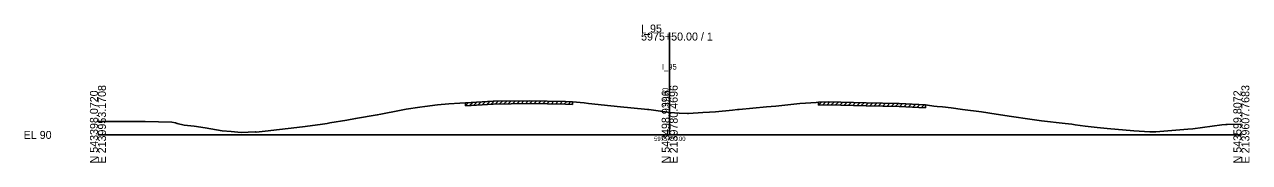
# Model space of a CAD drawing. Extents: x -12534 to 3403, y -1332 to 21983.
# Drawn here: x -25.7 to 402.8, y 10490.3 to 10538.7 of the extents above; entities that cross this region are included whole.
import ezdxf

# ---------------------------------------------------------------- set-up
doc = ezdxf.new("R2010")
doc.units = 0
for name, color, linetype in [('RD_GPK_XS_Cell', 7, 'Continuous'), ('RD_XS_ExGround', 7, 'Continuous'), ('RD_XS_ExPaveRet', 7, 'Continuous'), ('RD_XS_TX_Baseline', 7, 'Continuous'), ('RD_XS_TX_Elev_EX', 7, 'Continuous'), ('RD_XS_TX_Station', 7, 'Continuous')]:
    doc.layers.add(name, color=color, linetype=linetype)

msp = doc.modelspace()

# ---------------------------------------------------------------- linework, layer by layer
at = {"layer": 'RD_GPK_XS_Cell'}
for p, q in [((200, 10500), (200, 10535.9)), ((0, 10500), (200, 10500)), ((200, 10500), (400, 10500))]:
    msp.add_line(p, q, dxfattribs=at)
at = {"layer": 'RD_XS_ExGround'}
msp.add_lwpolyline([(0, 10504.65), (3.21, 10504.72), (6.72, 10504.76), (11.37, 10504.66), (16.54, 10504.66), (25.79, 10504.46), (27.18, 10504.26), (27.72, 10504), (30.17, 10503.47), (33.67, 10503.11), (37.47, 10502.48), (43.49, 10501.41), (46.58, 10501.24), (50.15, 10500.83), (54.96, 10501.08), (55.33, 10500.98), (58.45, 10501.27), (71.58, 10502.87), (77.73, 10503.71), (80.16, 10504.06), (81.1, 10504.23), (87.05, 10505.2), (90.13, 10505.7), (97.69, 10507.02), (98.97, 10507.28), (105.51, 10508.6), (107.79, 10508.99), (112.61, 10509.75), (114.37, 10510.02), (118.81, 10510.58), (122.7, 10510.92), (126.56, 10511.15), (128.53, 10511.25), (138.29, 10511.84), (150.82, 10511.97), (163.61, 10511.76), (165.97, 10511.66), (170.05, 10511.26), (171.63, 10511.01), (179.42, 10510.24), (182.76, 10509.87), (191.22, 10509.03), (192.3, 10508.92), (192.67, 10508.88), (200.1, 10507.89), (203.27, 10507.59), (206.19, 10507.54), (206.64, 10507.54), (211.57, 10507.84), (213.96, 10507.93), (216.02, 10508.13), (221.97, 10508.72), (223.72, 10508.89), (224.3, 10508.94), (233.87, 10509.81), (237.18, 10510.12), (245.53, 10510.96), (247.5, 10511.14), (251.27, 10511.37), (252.05, 10511.45), (255.46, 10511.59), (268.7, 10511.25), (280.29, 10511.02), (289.48, 10510.53), (290.21, 10510.4), (292.42, 10510.11), (293.53, 10510), (295.49, 10509.82), (298.43, 10509.45), (302.48, 10508.89), (309.09, 10508.06), (314.22, 10507.28), (319.58, 10506.44), (326, 10505.54), (330.09, 10504.99), (338.4, 10504.03), (340.65, 10503.76), (341.81, 10503.59), (345.31, 10503.04), (349.6, 10502.59), (353.05, 10502.29), (362.38, 10501.43), (367.98, 10501.06), (370.13, 10501.12), (381.22, 10501.96), (383.07, 10502.19), (393.12, 10503.51), (394.56, 10503.67), (395.01, 10503.69), (400, 10503.79)], dxfattribs=at)
at = {"layer": 'RD_XS_ExPaveRet'}
for p, q in [((145.03, 10510.91), (146.04, 10511.92)), ((146.53, 10510.92), (147.54, 10511.93)), ((148.03, 10510.94), (149.04, 10511.95)), ((149.53, 10510.95), (150.54, 10511.96)), ((151.03, 10510.96), (152.01, 10511.95)), ((152.53, 10510.94), (153.51, 10511.92)), ((128.53, 10510.25), (129.59, 10511.32)), ((128.53, 10510.25), (128.53, 10511.25)), ((128.53, 10510.25), (138.29, 10510.84)), ((130.03, 10510.34), (131.09, 10511.41)), ((131.53, 10510.43), (132.59, 10511.5)), ((133.03, 10510.52), (134.09, 10511.59)), ((134.53, 10510.61), (135.59, 10511.68)), ((136.03, 10510.71), (137.09, 10511.77)), ((137.53, 10510.8), (138.57, 10511.84)), ((138.29, 10510.84), (150.82, 10510.97)), ((139.03, 10510.85), (140.04, 10511.86)), ((140.53, 10510.86), (141.54, 10511.87)), ((142.03, 10510.88), (143.04, 10511.89)), ((143.53, 10510.89), (144.54, 10511.9)), ((150.82, 10510.97), (163.61, 10510.76)), ((154.03, 10510.92), (155.01, 10511.9)), ((155.53, 10510.89), (156.51, 10511.88)), ((157.03, 10510.87), (158.01, 10511.85)), ((158.53, 10510.84), (159.51, 10511.83)), ((160.03, 10510.82), (161.01, 10511.8)), ((161.53, 10510.8), (162.51, 10511.78)), ((163.03, 10510.77), (164, 10511.75)), ((163.61, 10510.76), (165.97, 10510.66)), ((164.53, 10510.72), (165.48, 10511.68)), ((165.97, 10511.66), (165.97, 10510.66)), ((252.05, 10510.45), (253.09, 10511.5)), ((252.05, 10510.45), (252.05, 10511.45)), ((252.05, 10510.45), (255.46, 10510.59)), ((253.55, 10510.51), (254.59, 10511.56)), ((255.05, 10510.58), (256.05, 10511.58)), ((255.46, 10510.59), (268.7, 10510.25)), ((256.55, 10510.56), (257.53, 10511.54)), ((258.05, 10510.53), (259.03, 10511.5)), ((259.55, 10510.49), (260.53, 10511.46)), ((261.05, 10510.45), (262.03, 10511.42)), ((262.55, 10510.41), (263.53, 10511.38)), ((264.05, 10510.37), (265.03, 10511.34)), ((265.55, 10510.33), (266.53, 10511.3)), ((267.05, 10510.29), (268.03, 10511.26)), ((268.55, 10510.25), (269.53, 10511.23)), ((268.7, 10510.25), (280.29, 10510.02)), ((270.05, 10510.22), (271.03, 10511.2)), ((271.55, 10510.19), (272.53, 10511.17)), ((273.05, 10510.16), (274.03, 10511.14)), ((274.55, 10510.13), (275.53, 10511.11)), ((276.05, 10510.1), (277.03, 10511.09)), ((277.55, 10510.08), (278.53, 10511.06)), ((279.05, 10510.05), (280.03, 10511.03)), ((280.29, 10510.02), (289.48, 10509.53)), ((280.55, 10510.01), (281.5, 10510.96)), ((282.05, 10509.93), (283, 10510.88)), ((283.55, 10509.85), (284.5, 10510.8)), ((285.05, 10509.77), (286, 10510.72)), ((286.55, 10509.69), (287.5, 10510.64)), ((288.05, 10509.61), (289, 10510.56)), ((289.48, 10510.53), (289.48, 10509.53))]:
    msp.add_line(p, q, dxfattribs=at)

# ---------------------------------------------------------------- texts
at = {"layer": 'RD_GPK_XS_Cell'}
for s, p in [('I_95', (190, 10535.9)), ('5975+50.00 / 1', (190, 10533.1)), ('EL 90', (-26, 10498.6))]:
    msp.add_text(s, height=2.8, dxfattribs=at).set_placement(p)
for s, p in [('E 2139953.1708', (2.8, 10490)), ('E 2139780.4696', (202.8, 10490)), ('E 2139607.7683', (402.8, 10490)), ('N 543398.0720', (0, 10490)), ('N 543498.9396', (200, 10490)), ('N 543599.8072', (400, 10490))]:
    msp.add_text(s, height=2.8, rotation=90, dxfattribs=at).set_placement(p)
at = {"layer": 'RD_XS_TX_Baseline'}
msp.add_text('I_95', height=2, dxfattribs=at).set_placement((197.28, 10522.9))
at = {"layer": 'RD_XS_TX_Elev_EX'}
msp.add_text('97.90', height=2, rotation=90, dxfattribs=at).set_placement((199.5, 10509.9))
at = {"layer": 'RD_XS_TX_Station'}
msp.add_text('5975+50.00', height=1.5, dxfattribs=at).set_placement((194.55, 10497.9))

doc.saveas('drawing.dxf')
